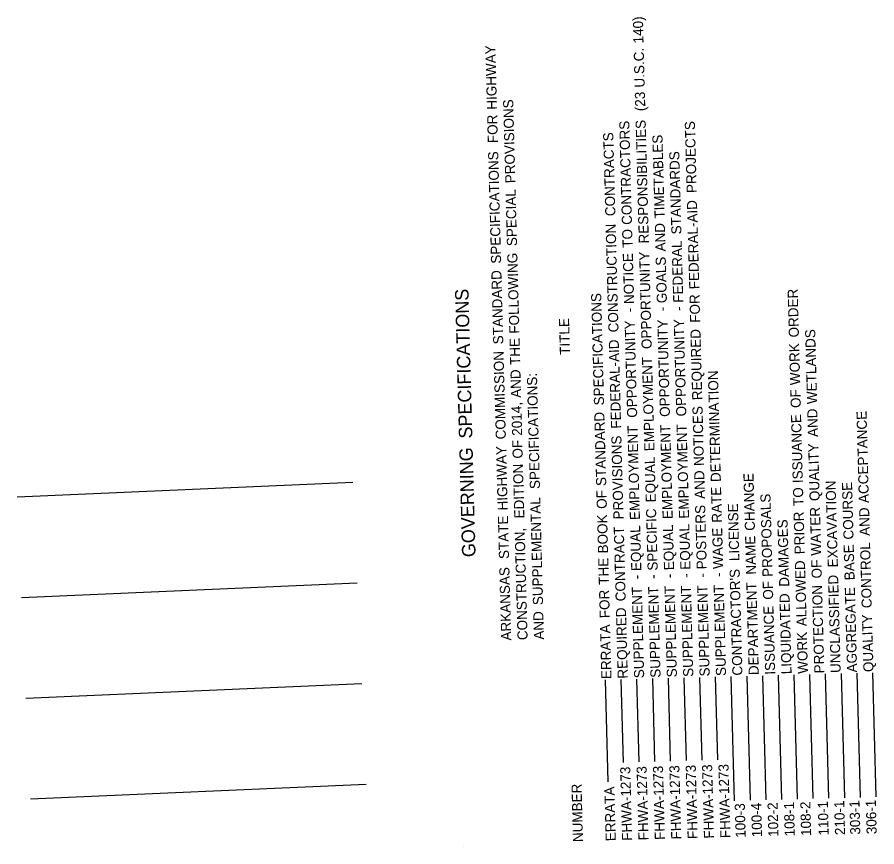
# Model space of a CAD drawing. Extents: x 1930579 to 1931706, y 595585 to 597808.
# Drawn here: x 1930579 to 1931091, y 596423 to 596917 of the extents above; entities that cross this region are included whole.
import ezdxf

# ---------------------------------------------------------------- set-up
doc = ezdxf.new("R2010")
doc.units = 0
for name, color, linetype in [('BR_Pr_Bent_CL', 7, 'Continuous'), ('Default', 7, 'Continuous'), ('R_No Plot', 7, 'Continuous')]:
    doc.layers.add(name, color=color, linetype=linetype)

msp = doc.modelspace()

# ---------------------------------------------------------------- linework, layer by layer
at = {"layer": 'BR_Pr_Bent_CL'}
for p, q in [((1930779.3, 596640.34), (1930579.49, 596631.64)), ((1930781.91, 596580.39), (1930582.1, 596571.7)), ((1930784.52, 596520.45), (1930584.71, 596511.76)), ((1930787.12, 596460.51), (1930587.31, 596451.81))]:
    msp.add_line(p, q, dxfattribs=at)
at = {"layer": 'Default'}
for p, q in [((1930977.74, 596474.75), (1930976.42, 596524.06)), ((1930987.1, 596475), (1930985.77, 596524.31)), ((1930996.45, 596475.25), (1930995.13, 596524.56)), ((1931006.47, 596450.89), (1931004.49, 596524.81)), ((1931015.83, 596451.14), (1931013.84, 596525.06)), ((1931025.18, 596451.39), (1931023.2, 596525.31)), ((1931034.54, 596451.64), (1931032.56, 596525.56)), ((1931043.9, 596451.89), (1931041.91, 596525.82)), ((1931053.25, 596452.15), (1931051.27, 596526.07)), ((1931062.61, 596452.4), (1931060.63, 596526.32)), ((1931071.97, 596452.65), (1931069.98, 596526.57)), ((1931081.32, 596452.9), (1931079.34, 596526.82)), ((1931090.68, 596453.15), (1931088.7, 596527.07)), ((1930931.26, 596462.19), (1930929.63, 596522.8)), ((1930940.31, 596473.74), (1930938.99, 596523.05)), ((1930949.67, 596473.99), (1930948.35, 596523.3)), ((1930959.03, 596474.25), (1930957.7, 596523.56)), ((1930968.38, 596474.5), (1930967.06, 596523.81))]:
    msp.add_line(p, q, dxfattribs=at)
at = {"layer": 'R_No Plot'}
msp.add_line((1930845.36, 596423.48), (1930845.36, 596423.48), dxfattribs=at)

# ---------------------------------------------------------------- texts
at = {"layer": 'Default'}
for s, height, p in [(' 140)', 6, (1930952.33, 596899.44)), (' HIGHWAY', 6, (1930865.12, 596860)), (' U.S.C.', 6, (1930953.03, 596873.17)), (' (23', 6, (1930953.41, 596859.11)), (' PROVISIONS', 6, (1930876.05, 596816.23)), (' FOR', 6, (1930865.65, 596840.1)), (' CONTRACTORS', 6, (1930945.47, 596791.46)), (' RESPONSIBILITIES', 6, (1930955.52, 596780.38)), (' PROJECTS', 6, (1930983.98, 596810.42)), (' CONTRACTS', 6, (1930935.58, 596796.64)), (' TIMETABLES', 6, (1930964.88, 596795.19)), (' SPECIFICATIONS', 6, (1930867.58, 596768.36)), (' STANDARDS', 6, (1930974.89, 596785.8)), (' SPECIAL', 6, (1930877.05, 596778.79)), (' FEDERAL-AID', 6, (1930985.52, 596753.13)), (' CONSTRUCTION', 6, (1930937.44, 596727.48)), (' TO', 6, (1930945.84, 596777.87)), (' AND', 6, (1930965.41, 596775.62)), (' FEDERAL', 6, (1930975.98, 596745.11)), (' FOLLOWING', 6, (1930878.45, 596726.71)), (' NOTICE', 6, (1930946.74, 596744.33)), (' OPPORTUNITY', 6, (1930957.21, 596717.58)), (' GOALS', 6, (1930966.23, 596744.85)), (' STANDARD', 6, (1930868.87, 596720.37)), (' SPECIFICATIONS', 8, (1930850.48, 596663.59)), (' ORDER', 6, (1931044.81, 596724.46)), (' SPECIFICATIONS', 6, (1930928.85, 596684.02)), (' FOR', 6, (1930986.05, 596733.22)), (' -', 6, (1930946.87, 596739.47)), (' -', 6, (1930966.36, 596740)), (' -', 6, (1930976.11, 596740.26)), ('TITLE', 6, (1930908.48, 596716.34)), (' OPPORTUNITY', 6, (1930948.56, 596676.67)), (' OPPORTUNITY', 6, (1930968.05, 596677.2)), (' OPPORTUNITY', 6, (1930977.79, 596677.46)), (' REQUIRED', 6, (1930987.29, 596687.11)), (' WETLANDS', 6, (1931055.63, 596684.79)), (' THE', 6, (1930878.95, 596708.07)), (' FEDERAL-AID', 6, (1930938.98, 596670.19)), (' WORK', 6, (1931045.57, 596696.08)), (' COMMISSION', 6, (1930870.39, 596663.79)), (' EMPLOYMENT', 6, (1930958.84, 596656.75)), (' AND', 6, (1930879.48, 596688.49)), (' SPECIFICATIONS:', 6, (1930890.69, 596634.25)), (' DETERMINATION', 6, (1930998.35, 596638.43)), (' OF', 6, (1931045.93, 596682.49)), (' 2014,', 6, (1930880.08, 596665.95)), (' NOTICES', 6, (1930988.34, 596647.96)), (' AND', 6, (1931056.15, 596665.21)), (' ACCEPTANCE', 6, (1931086.47, 596625.93)), (' STANDARD', 6, (1930930.14, 596636.04)), (' ISSUANCE', 6, (1931047.13, 596637.77)), (' EMPLOYMENT', 6, (1930950.19, 596615.84)), (' EMPLOYMENT', 6, (1930969.68, 596616.36)), (' EMPLOYMENT', 6, (1930979.43, 596616.63)), (' PROVISIONS', 6, (1930940.43, 596616.14)), (' OF', 6, (1930880.45, 596652.37)), (' QUALITY', 6, (1931057.17, 596627.09)), ('GOVERNING', 8, (1930852.3, 596595.96)), (' HIGHWAY', 6, (1930871.52, 596621.49)), (' EQUAL', 6, (1930959.66, 596626.31)), (' EDITION', 6, (1930881.4, 596616.74)), (' AND', 6, (1930988.87, 596628.39)), (' CHANGE', 6, (1931018.64, 596609.39)), (' RATE', 6, (1930999, 596614.2)), (' TO', 6, (1931047.5, 596624.18)), (' EXCAVATION', 6, (1931067.99, 596587.59)), (' COURSE', 6, (1931077.3, 596604.18)), (' SUPPLEMENTAL', 6, (1930892.54, 596565.15)), (' OF', 6, (1930930.5, 596622.46)), (' PROPOSALS', 6, (1931029.13, 596581.97)), (' POSTERS', 6, (1930989.99, 596586.45)), (' LICENSE', 6, (1931009.37, 596591.35)), (' BOOK', 6, (1930931.22, 596595.93)), (' SPECIFIC', 6, (1930960.75, 596585.66)), (' PRIOR', 6, (1931048.27, 596595.42)), (' WATER', 6, (1931058.05, 596594.61)), (' AND', 6, (1931086.99, 596606.36)), (' STATE', 6, (1930872.3, 596592.6)), (' DAMAGES', 6, (1931039.04, 596576.09)), ('           CONSTRUCTION,', 6, (1930883.94, 596522.05)), (' CONTRACT', 6, (1930941.73, 596567.42)), (' EQUAL', 6, (1930951.01, 596585.4)), (' EQUAL', 6, (1930970.5, 596585.92)), (' EQUAL', 6, (1930980.24, 596586.18)), (' WAGE', 6, (1930999.74, 596586.71)), (' NAME', 6, (1931019.34, 596583.3)), (' BASE', 6, (1931077.95, 596579.94)), (' CONTROL', 6, (1931088.15, 596563.35)), (' THE', 6, (1930931.72, 596577.29)), (' ALLOWED', 6, (1931049.42, 596552.56)), (' OF', 6, (1931058.41, 596581.03)), ('           ARKANSAS', 6, (1930874.2, 596521.79)), (' -', 6, (1930960.88, 596580.81)), (' -', 6, (1930970.63, 596581.07)), (' -', 6, (1930980.38, 596581.33)), (' -', 6, (1930990.12, 596581.59)), (' -', 6, (1930999.87, 596581.85)), ("CONTRACTOR'S", 6, (1931011.14, 596525.46)), (' -', 6, (1930951.14, 596580.54)), ('DEPARTMENT', 6, (1931020.88, 596525.72)), (' OF', 6, (1931029.49, 596568.39)), ('UNCLASSIFIED', 6, (1931069.61, 596527.03)), (' FOR', 6, (1930932.25, 596557.38)), ('SUPPLEMENT', 6, (1930952.66, 596523.89)), ('SUPPLEMENT', 6, (1930962.4, 596524.15)), ('SUPPLEMENT', 6, (1930972.15, 596524.42)), ('SUPPLEMENT', 6, (1930981.9, 596524.68)), ('SUPPLEMENT', 6, (1930991.64, 596524.94)), ('SUPPLEMENT', 6, (1931001.39, 596525.2)), ('PROTECTION', 6, (1931059.87, 596526.77)), ('AGGREGATE', 6, (1931079.36, 596527.29)), ('LIQUIDATED', 6, (1931040.37, 596526.25)), ('REQUIRED', 6, (1930942.91, 596523.63)), ('ISSUANCE', 6, (1931030.63, 596525.99)), ('           AND', 6, (1930893.69, 596522.31)), ('QUALITY', 6, (1931089.11, 596527.56)), ('ERRATA', 6, (1930933.16, 596523.37)), ('WORK', 6, (1931050.12, 596526.51)), ('FHWA-1273', 6, (1930945.5, 596427.14)), ('FHWA-1273', 6, (1930955.25, 596427.4)), ('FHWA-1273', 6, (1930964.99, 596427.66)), ('FHWA-1273', 6, (1930974.74, 596427.93)), ('FHWA-1273', 6, (1930984.49, 596428.19)), ('FHWA-1273', 6, (1930994.23, 596428.45)), ('FHWA-1273', 6, (1931003.98, 596428.71)), ('NUMBER', 6, (1930916.26, 596426.36)), ('ERRATA', 6, (1930935.75, 596426.88)), ('100-3', 6, (1931013.05, 596428.95)), ('100-4', 6, (1931022.8, 596429.22)), ('102-2', 6, (1931032.54, 596429.48)), ('108-1', 6, (1931042.29, 596429.74)), ('108-2', 6, (1931052.04, 596430)), ('110-1', 6, (1931062.46, 596430.28)), ('210-1', 6, (1931072.2, 596430.54)), ('303-1', 6, (1931081.28, 596430.79)), ('306-1', 6, (1931091.02, 596431.05))]:
    msp.add_text(s, height=height, rotation=91.5377, dxfattribs=at).set_placement(p)

doc.saveas('drawing.dxf')
